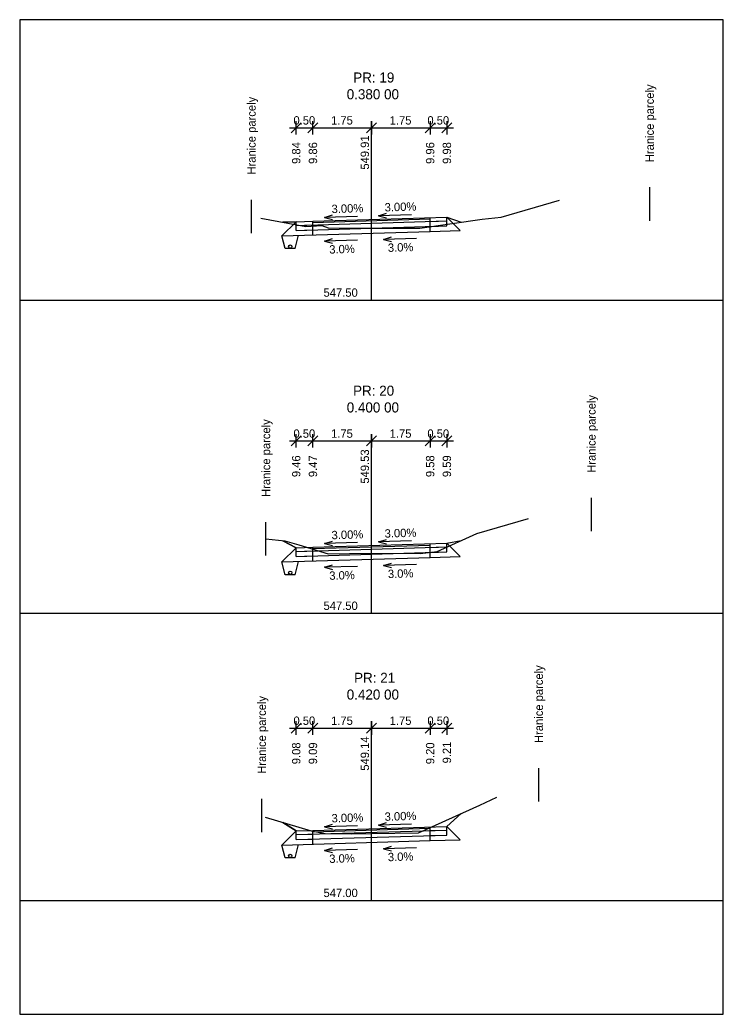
# Model space of a CAD drawing. Extents: x -603737 to -603383, y -1112154 to -1112124.
# Drawn here: x -603556.53 to -603535.53, y -1112153.84 to -1112124.14 of the extents above; entities that cross this region are included whole.
import ezdxf

# ---------------------------------------------------------------- set-up
doc = ezdxf.new("R2010")
doc.units = 0
for name, color, linetype in [('_křivky z hran', 7, 'Continuous'), ('_netisk', 7, 'Continuous'), ('C3D_Podsestava-Popis', 7, 'Continuous'), ('C3D_PP-Popisek', 7, 'Continuous'), ('C3D_PR', 7, 'Continuous'), ('C3D_ZPR', 7, 'Continuous'), ('Default', 7, 'Continuous'), ('konstrukce', 7, 'Continuous')]:
    doc.layers.add(name, color=color, linetype=linetype)

# ---------------------------------------------------------------- blocks, each defined once
blk = doc.blocks.new('_Oblique')
at = {"layer": 'Default'}
blk.add_line((-0.5, -0.5), (0.5, 0.5), dxfattribs=at)
blk = doc.blocks.new('AeccTickLine')
at = {"layer": 'Default'}
blk.add_line((0, 1), (0, -1), dxfattribs=at)

msp = doc.modelspace()

# ---------------------------------------------------------------- linework, layer by layer
at = {"layer": '_netisk'}
msp.add_lwpolyline([(-603556.532, -1112153.84), (-603535.532, -1112153.84), (-603535.532, -1112124.14), (-603556.532, -1112124.14)], close=True, dxfattribs=at)
at = {"layer": 'C3D_Podsestava-Popis'}
for p, q in [((-603548.482, -1112127.361), (-603546.032, -1112127.361)), ((-603546.032, -1112127.361), (-603543.582, -1112127.361)), ((-603546.032, -1112128.101), (-603546.032, -1112127.511)), ((-603548.482, -1112136.717), (-603546.032, -1112136.717)), ((-603546.032, -1112136.717), (-603543.582, -1112136.717)), ((-603546.032, -1112137.841), (-603546.032, -1112136.867)), ((-603548.482, -1112145.294), (-603546.032, -1112145.294)), ((-603546.032, -1112145.294), (-603543.582, -1112145.294)), ((-603546.032, -1112146.299), (-603546.032, -1112145.444))]:
    msp.add_line(p, q, dxfattribs=at)
at = {"layer": 'C3D_PP-Popisek'}
for p, q in [((-603547.435, -1112130.039), (-603547.198, -1112129.964)), ((-603546.451, -1112130.009), (-603547.435, -1112130.039)), ((-603547.435, -1112130.039), (-603547.194, -1112130.1)), ((-603545.824, -1112129.99), (-603545.587, -1112129.915)), ((-603544.84, -1112129.961), (-603545.824, -1112129.99)), ((-603545.824, -1112129.99), (-603545.583, -1112130.051)), ((-603547.435, -1112130.749), (-603547.198, -1112130.674)), ((-603546.451, -1112130.72), (-603547.435, -1112130.749)), ((-603547.435, -1112130.749), (-603547.194, -1112130.81)), ((-603545.67, -1112130.696), (-603545.434, -1112130.621)), ((-603544.687, -1112130.667), (-603545.67, -1112130.696)), ((-603545.67, -1112130.696), (-603545.43, -1112130.757)), ((-603545.824, -1112139.735), (-603545.587, -1112139.659)), ((-603547.435, -1112139.783), (-603547.198, -1112139.708)), ((-603546.451, -1112139.754), (-603547.435, -1112139.783)), ((-603547.435, -1112139.783), (-603547.194, -1112139.844)), ((-603544.84, -1112139.705), (-603545.824, -1112139.735)), ((-603545.824, -1112139.735), (-603545.583, -1112139.796)), ((-603547.435, -1112140.493), (-603547.198, -1112140.418)), ((-603546.451, -1112140.464), (-603547.435, -1112140.493)), ((-603547.435, -1112140.493), (-603547.194, -1112140.554)), ((-603545.67, -1112140.44), (-603545.434, -1112140.365)), ((-603544.687, -1112140.411), (-603545.67, -1112140.44)), ((-603545.67, -1112140.44), (-603545.43, -1112140.501)), ((-603547.435, -1112148.241), (-603547.198, -1112148.166)), ((-603546.451, -1112148.212), (-603547.435, -1112148.241)), ((-603547.435, -1112148.241), (-603547.194, -1112148.302)), ((-603545.824, -1112148.193), (-603545.587, -1112148.117)), ((-603544.84, -1112148.163), (-603545.824, -1112148.193)), ((-603545.824, -1112148.193), (-603545.583, -1112148.254)), ((-603545.67, -1112148.899), (-603545.434, -1112148.823)), ((-603544.687, -1112148.869), (-603545.67, -1112148.899)), ((-603547.435, -1112148.951), (-603547.198, -1112148.876)), ((-603546.451, -1112148.922), (-603547.435, -1112148.951)), ((-603547.435, -1112148.951), (-603547.194, -1112149.013)), ((-603545.67, -1112148.899), (-603545.43, -1112148.96))]:
    msp.add_line(p, q, dxfattribs=at)
at = {"layer": 'C3D_PR'}
for points in [[(-603549.332, -1112130.068), (-603547.992, -1112130.31), (-603547.511, -1112130.284), (-603547.329, -1112130.351), (-603546.032, -1112130.358), (-603545.362, -1112130.362), (-603544.593, -1112130.364), (-603542.725, -1112130.092), (-603542.157, -1112130.03), (-603540.414, -1112129.522)], [(-603549.19, -1112139.642), (-603548.619, -1112139.705), (-603548.2, -1112139.82), (-603547.323, -1112140.088), (-603546.051, -1112140.069), (-603546.032, -1112140.069), (-603544.582, -1112140.076), (-603544.068, -1112140.018), (-603542.889, -1112139.482), (-603541.343, -1112139.031)], [(-603549.208, -1112147.953), (-603547.833, -1112148.367), (-603547.411, -1112148.443), (-603546.633, -1112148.454), (-603546.032, -1112148.446), (-603544.628, -1112148.426), (-603542.797, -1112147.594), (-603542.289, -1112147.356)]]:
    msp.add_lwpolyline(points, dxfattribs=at)
at = {"layer": 'C3D_ZPR'}
for p, q in [((-603546.032, -1112132.511), (-603546.032, -1112127.511)), ((-603537.725, -1112130.141), (-603537.725, -1112129.141)), ((-603549.617, -1112130.511), (-603549.617, -1112129.511)), ((-603548.282, -1112130.278), (-603543.782, -1112130.143)), ((-603548.282, -1112130.168), (-603547.782, -1112130.153)), ((-603547.782, -1112130.153), (-603543.782, -1112130.033)), ((-603547.782, -1112130.193), (-603544.282, -1112130.088)), ((-603547.782, -1112130.563), (-603547.782, -1112130.153)), ((-603544.282, -1112130.088), (-603544.282, -1112130.048)), ((-603544.282, -1112130.458), (-603544.282, -1112130.048)), ((-603544.282, -1112130.158), (-603543.782, -1112130.143)), ((-603544.282, -1112130.308), (-603544.282, -1112130.158)), ((-603543.782, -1112130.293), (-603543.782, -1112130.033)), ((-603543.782, -1112130.293), (-603543.782, -1112130.033)), ((-603543.782, -1112130.033), (-603543.384, -1112130.431)), ((-603543.782, -1112130.033), (-603543.357, -1112130.184)), ((-603543.782, -1112130.033), (-603543.357, -1112130.184)), ((-603548.705, -1112130.591), (-603548.282, -1112130.168)), ((-603548.705, -1112130.591), (-603544.282, -1112130.458)), ((-603548.282, -1112130.168), (-603548.677, -1112130.186)), ((-603548.677, -1112130.186), (-603548.282, -1112130.168)), ((-603548.282, -1112130.428), (-603548.282, -1112130.168)), ((-603548.282, -1112130.428), (-603548.282, -1112130.168)), ((-603548.282, -1112130.278), (-603547.782, -1112130.263)), ((-603548.282, -1112130.428), (-603543.782, -1112130.293)), ((-603548.282, -1112130.428), (-603547.782, -1112130.413)), ((-603547.782, -1112130.263), (-603547.782, -1112130.193)), ((-603547.782, -1112130.563), (-603547.782, -1112130.413)), ((-603544.282, -1112130.308), (-603543.782, -1112130.293)), ((-603544.282, -1112130.458), (-603543.384, -1112130.431)), ((-603556.532, -1112132.511), (-603535.532, -1112132.511)), ((-603546.032, -1112141.867), (-603546.032, -1112136.867)), ((-603539.465, -1112139.418), (-603539.465, -1112138.418)), ((-603549.183, -1112140.142), (-603549.183, -1112139.142)), ((-603548.705, -1112140.331), (-603548.282, -1112139.909)), ((-603548.282, -1112139.909), (-603548.677, -1112139.698)), ((-603548.677, -1112139.698), (-603548.282, -1112139.909)), ((-603548.282, -1112140.019), (-603543.782, -1112139.884)), ((-603548.282, -1112139.909), (-603547.782, -1112139.894)), ((-603548.282, -1112140.169), (-603548.282, -1112139.909)), ((-603548.282, -1112140.169), (-603548.282, -1112139.909)), ((-603547.782, -1112139.894), (-603543.782, -1112139.774)), ((-603547.782, -1112139.934), (-603544.282, -1112139.829)), ((-603547.782, -1112140.304), (-603547.782, -1112139.894)), ((-603547.782, -1112140.004), (-603547.782, -1112139.934)), ((-603544.282, -1112139.829), (-603544.282, -1112139.789)), ((-603544.282, -1112140.199), (-603544.282, -1112139.789)), ((-603544.282, -1112139.899), (-603543.782, -1112139.884)), ((-603544.282, -1112140.049), (-603544.282, -1112139.899)), ((-603543.782, -1112139.774), (-603543.357, -1112139.695)), ((-603543.782, -1112139.774), (-603543.357, -1112139.695)), ((-603543.782, -1112140.034), (-603543.782, -1112139.774)), ((-603543.782, -1112140.034), (-603543.782, -1112139.774)), ((-603543.782, -1112139.774), (-603543.384, -1112140.172)), ((-603548.705, -1112140.331), (-603544.282, -1112140.199)), ((-603548.282, -1112140.019), (-603547.782, -1112140.004)), ((-603548.282, -1112140.169), (-603543.782, -1112140.034)), ((-603548.282, -1112140.169), (-603547.782, -1112140.154)), ((-603547.782, -1112140.304), (-603547.782, -1112140.154)), ((-603544.282, -1112140.049), (-603543.782, -1112140.034)), ((-603544.282, -1112140.199), (-603543.384, -1112140.172)), ((-603556.532, -1112141.867), (-603535.532, -1112141.867)), ((-603546.032, -1112150.444), (-603546.032, -1112145.444)), ((-603541.038, -1112147.492), (-603541.038, -1112146.492)), ((-603549.309, -1112148.409), (-603549.309, -1112147.409)), ((-603543.782, -1112148.232), (-603543.357, -1112147.849)), ((-603543.782, -1112148.232), (-603543.357, -1112147.849)), ((-603548.282, -1112148.367), (-603548.677, -1112148.113)), ((-603548.677, -1112148.113), (-603548.282, -1112148.367)), ((-603547.782, -1112148.352), (-603543.782, -1112148.232)), ((-603544.282, -1112148.287), (-603544.282, -1112148.247)), ((-603544.282, -1112148.657), (-603544.282, -1112148.247)), ((-603543.782, -1112148.492), (-603543.782, -1112148.232)), ((-603543.782, -1112148.492), (-603543.782, -1112148.232)), ((-603543.782, -1112148.232), (-603543.384, -1112148.63)), ((-603548.705, -1112148.789), (-603548.282, -1112148.367)), ((-603548.282, -1112148.477), (-603543.782, -1112148.342)), ((-603548.282, -1112148.367), (-603547.782, -1112148.352)), ((-603548.282, -1112148.627), (-603548.282, -1112148.367)), ((-603548.282, -1112148.627), (-603548.282, -1112148.367)), ((-603548.282, -1112148.477), (-603547.782, -1112148.462)), ((-603548.282, -1112148.627), (-603543.782, -1112148.492)), ((-603547.782, -1112148.392), (-603544.282, -1112148.287)), ((-603547.782, -1112148.762), (-603547.782, -1112148.352)), ((-603547.782, -1112148.462), (-603547.782, -1112148.392)), ((-603544.282, -1112148.357), (-603543.782, -1112148.342)), ((-603544.282, -1112148.507), (-603544.282, -1112148.357)), ((-603544.282, -1112148.507), (-603543.782, -1112148.492)), ((-603548.705, -1112148.789), (-603544.282, -1112148.657)), ((-603548.282, -1112148.627), (-603547.782, -1112148.612)), ((-603547.782, -1112148.762), (-603547.782, -1112148.612)), ((-603544.282, -1112148.657), (-603543.384, -1112148.63)), ((-603556.532, -1112150.444), (-603535.532, -1112150.444))]:
    msp.add_line(p, q, dxfattribs=at)
at = {"layer": 'konstrukce'}
for p, q in [((-603548.609, -1112130.972), (-603548.705, -1112130.587)), ((-603548.309, -1112130.972), (-603548.209, -1112130.572)), ((-603548.309, -1112130.972), (-603548.609, -1112130.972)), ((-603548.609, -1112140.716), (-603548.705, -1112140.331)), ((-603548.309, -1112140.716), (-603548.209, -1112140.316)), ((-603548.309, -1112140.716), (-603548.609, -1112140.716)), ((-603548.609, -1112149.175), (-603548.705, -1112148.789)), ((-603548.309, -1112149.175), (-603548.209, -1112148.775)), ((-603548.309, -1112149.175), (-603548.609, -1112149.175))]:
    msp.add_line(p, q, dxfattribs=at)
for centre in [(-603548.459, -1112130.912), (-603548.459, -1112140.656), (-603548.459, -1112149.115)]:
    msp.add_circle(centre, 0.05, dxfattribs=at)

# ---------------------------------------------------------------- block references
at = {"layer": '_křivky z hran', "rotation": 180}
for name, p, xscale, yscale in [('AeccTickLine', (-603548.282, -1112127.361), 0.2, 0.20000000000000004), ('AeccTickLine', (-603547.782, -1112127.361), 0.2, 0.20000000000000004), ('AeccTickLine', (-603546.032, -1112127.361), 0.2, 0.20000000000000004), ('_Oblique', (-603548.282, -1112127.361), 0.3, 0.3), ('_Oblique', (-603547.782, -1112127.361), 0.3, 0.3), ('_Oblique', (-603546.032, -1112127.361), 0.3, 0.3), ('_Oblique', (-603548.282, -1112136.717), 0.3, 0.3), ('AeccTickLine', (-603548.282, -1112136.717), 0.2, 0.20000000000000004), ('_Oblique', (-603547.782, -1112136.717), 0.3, 0.3), ('AeccTickLine', (-603547.782, -1112136.717), 0.2, 0.20000000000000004), ('_Oblique', (-603546.032, -1112136.717), 0.3, 0.3), ('AeccTickLine', (-603546.032, -1112136.717), 0.2, 0.20000000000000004), ('_Oblique', (-603548.282, -1112145.294), 0.3, 0.3), ('AeccTickLine', (-603548.282, -1112145.294), 0.2, 0.20000000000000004), ('_Oblique', (-603547.782, -1112145.294), 0.3, 0.3), ('AeccTickLine', (-603547.782, -1112145.294), 0.2, 0.20000000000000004), ('_Oblique', (-603546.032, -1112145.294), 0.3, 0.3), ('AeccTickLine', (-603546.032, -1112145.294), 0.2, 0.20000000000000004)]:
    msp.add_blockref(name, p, dxfattribs=dict(at, xscale=xscale, yscale=yscale))
at = {"layer": '_křivky z hran'}
for name, p, xscale, yscale in [('AeccTickLine', (-603546.032, -1112127.361), 0.2, 0.20000000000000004), ('AeccTickLine', (-603544.282, -1112127.361), 0.2, 0.20000000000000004), ('AeccTickLine', (-603543.782, -1112127.361), 0.2, 0.20000000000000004), ('_Oblique', (-603546.032, -1112127.361), 0.3, 0.3), ('_Oblique', (-603544.282, -1112127.361), 0.3, 0.3), ('_Oblique', (-603543.782, -1112127.361), 0.3, 0.3), ('_Oblique', (-603546.032, -1112136.717), 0.3, 0.3), ('AeccTickLine', (-603546.032, -1112136.717), 0.2, 0.20000000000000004), ('_Oblique', (-603544.282, -1112136.717), 0.3, 0.3), ('AeccTickLine', (-603544.282, -1112136.717), 0.2, 0.20000000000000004), ('_Oblique', (-603543.782, -1112136.717), 0.3, 0.3), ('AeccTickLine', (-603543.782, -1112136.717), 0.2, 0.20000000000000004), ('_Oblique', (-603546.032, -1112145.294), 0.3, 0.3), ('AeccTickLine', (-603546.032, -1112145.294), 0.2, 0.20000000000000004), ('_Oblique', (-603544.282, -1112145.294), 0.3, 0.3), ('AeccTickLine', (-603544.282, -1112145.294), 0.2, 0.20000000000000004), ('_Oblique', (-603543.782, -1112145.294), 0.3, 0.3), ('AeccTickLine', (-603543.782, -1112145.294), 0.2, 0.20000000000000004)]:
    msp.add_blockref(name, p, dxfattribs=dict(at, xscale=xscale, yscale=yscale))

# ---------------------------------------------------------------- texts
at = {"layer": 'C3D_Podsestava-Popis'}
for s, rotation, p in [('0.50', 360, (-603548.363, -1112127.267)), ('1.75', 360, (-603547.24, -1112127.267)), ('1.75', 360, (-603547.24, -1112127.267)), ('1.75', 360, (-603545.49, -1112127.267)), ('1.75', 360, (-603545.49, -1112127.267)), ('0.50', 360, (-603544.363, -1112127.267)), ('549.91', 90, (-603546.106, -1112128.613)), ('9.84', 90, (-603548.156, -1112128.443)), ('9.84', 90, (-603548.156, -1112128.443)), ('9.86', 90, (-603547.656, -1112128.443)), ('9.96', 90, (-603544.156, -1112128.443)), ('9.98', 90, (-603543.656, -1112128.443)), ('9.98', 90, (-603543.656, -1112128.443)), ('3.00%', 1.7184, (-603547.222, -1112129.913)), ('3.00%', 1.7184, (-603545.637, -1112129.864)), ('3.0%', 1.7184, (-603547.29, -1112131.124)), ('3.0%', 1.7184, (-603545.54, -1112131.071)), ('0.50', 360, (-603548.363, -1112136.623)), ('1.75', 360, (-603547.24, -1112136.623)), ('1.75', 360, (-603547.24, -1112136.623)), ('1.75', 360, (-603545.49, -1112136.623)), ('1.75', 360, (-603545.49, -1112136.623)), ('0.50', 360, (-603544.363, -1112136.623)), ('549.53', 90, (-603546.106, -1112137.993)), ('9.46', 90, (-603548.156, -1112137.799)), ('9.46', 90, (-603548.156, -1112137.799)), ('9.47', 90, (-603547.656, -1112137.799)), ('9.58', 90, (-603544.156, -1112137.799)), ('9.59', 90, (-603543.656, -1112137.799)), ('9.59', 90, (-603543.656, -1112137.799)), ('3.00%', 1.7184, (-603545.637, -1112139.608)), ('3.00%', 1.7184, (-603547.222, -1112139.657)), ('3.0%', 1.7184, (-603545.54, -1112140.816)), ('3.0%', 1.7184, (-603547.29, -1112140.868)), ('0.50', 360, (-603548.363, -1112145.2)), ('1.75', 360, (-603547.24, -1112145.2)), ('1.75', 360, (-603547.24, -1112145.2)), ('1.75', 360, (-603545.49, -1112145.2)), ('1.75', 360, (-603545.49, -1112145.2)), ('0.50', 360, (-603544.363, -1112145.2)), ('549.14', 90, (-603546.106, -1112146.569)), ('9.08', 90, (-603548.156, -1112146.376)), ('9.08', 90, (-603548.156, -1112146.376)), ('9.09', 90, (-603547.656, -1112146.376)), ('9.20', 90, (-603544.156, -1112146.375)), ('9.21', 90, (-603543.656, -1112146.351)), ('9.21', 90, (-603543.656, -1112146.351)), ('3.00%', 1.7184, (-603547.222, -1112148.115)), ('3.00%', 1.7184, (-603545.637, -1112148.067)), ('3.0%', 1.7184, (-603547.29, -1112149.326)), ('3.0%', 1.7184, (-603545.54, -1112149.274))]:
    msp.add_text(s, height=0.25, rotation=rotation, dxfattribs=at).set_placement(p)
at = {"layer": 'C3D_ZPR'}
for s, p in [('PR: 19', (-603546.577, -1112126.011)), ('0.380 00', (-603546.772, -1112126.511)), ('PR: 20', (-603546.582, -1112135.367)), ('0.400 00', (-603546.772, -1112135.867)), ('PR: 21', (-603546.552, -1112143.944)), ('0.420 00', (-603546.772, -1112144.444))]:
    msp.add_text(s, height=0.3, dxfattribs=at).set_placement(p)
for s, rotation, p in [('Hranice parcely', 90, (-603537.6, -1112128.391)), ('Hranice parcely', 90, (-603549.492, -1112128.761)), ('547.50', 360, (-603547.465, -1112132.411)), ('Hranice parcely', 90, (-603539.34, -1112137.668)), ('Hranice parcely', 90, (-603549.058, -1112138.392)), ('547.50', 360, (-603547.465, -1112141.767)), ('Hranice parcely', 90, (-603540.913, -1112145.742)), ('Hranice parcely', 90, (-603549.184, -1112146.659)), ('547.00', 360, (-603547.465, -1112150.344))]:
    msp.add_text(s, height=0.25, rotation=rotation, dxfattribs=at).set_placement(p)

doc.saveas('drawing.dxf')
